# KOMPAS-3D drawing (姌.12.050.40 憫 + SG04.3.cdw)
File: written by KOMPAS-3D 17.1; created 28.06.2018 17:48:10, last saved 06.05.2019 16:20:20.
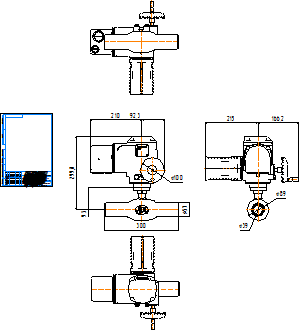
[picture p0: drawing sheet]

Sheet 1: A4, portrait

Title block, sheet 1: name: КШ.12.050.40 СС + SG04.3; material: Внимание! Данный продукт является объектом авторского права ООО «Торговый Дом АДЛ». / Запрещается изменение, копирование, распространение / (в том числе путем копирования на другие сайты и ресурсы в Интернете) / или любое иное использование информации и объектов без предварительного / согласия правообладателя (ООО «Торговый Дом АДЛ»).; sheets: 1; organisation: ООО "Торговый дом АДЛ"; sheet format: A4; stored path: C:\Users\tra\Desktop\2д чертежи\Шаровые краны БИВАЛ\КШ_Бивал_серия_11_12\KOMPAS_2D\КШ.12.050.40 СС + SG04.3.cdw

Views: Проекционный вид 3, Проекционный вид 4
Referenced files in C:\Users\tra\Desktop\2д чертежи\Шаровые краны БИВАЛ\КШ_Бивал_серия_11_12\KOMPAS_2D\: АПТА.0203-1704.04.01 _ Корпус крана Ду50 (Труба по ГОСТ).m3d, АПТА.0203-2615.11.01 _ Шар Ду50.m3d, АПТА.0203-2613.11.01 _ Шток Ду40-50.m3d, АПТА.0203-2613.12.01 _ Корпус штока Ду40-50.m3d, кольцо_проклад_40-50.m3d, шайба_штока_ду40-50.m3d, шайба_фрикц_40-50.m3d, подкладка_для_кольца_40-50.m3d, кольцо_упл_епдм.m3d, кольцо_упл_вит.m3d, СедлоДу50.m3d, Кольцо+опорное_Ду50.m3d, АПТА.0203-1704.03.01 _ Патрубок сварной точенный Ду50 (труба по ГОСТ).m3d, АПТА.0203-2615.02.02 _ Кольцо горловое Ду50.m3d, АПТА.0203-2615.02.03 _ Пружина тарельчатая Ду50.m3d
Referenced files in C:\Users\kka\KOMPAS_Work\Удлинения БИВАЛ ф. ADL\Небюджет\Специальные ISO фланцы\: Фланец Ду40-50.m3d
Referenced files in C:\Users\kka\KOMPAS_Work\!Trash\Электроприводы\: SG 04.3-F07.m3d
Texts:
  kka
  adl
  АПТА.0203-1704.04.01
  Корпус крана Ду50 (Труба по ГОСТ)
  АПТА.0203-2615.11.01
  Шар Ду50
  АПТА.0203-2613.11.01
  Шток Ду40-50
  АПТА.0203-2613.12.01
  Корпус штока Ду40-50
  АПТА.0203-2613.11.06
  Кольцо прокладочное Ду40-50
  АПТА.0203-2613.11.05
  Шайба штока Ду40-50
  АПТА.0203-2613.11.03
  Шайба фрикционная Ду40-50
  АПТА.0203-2613.11.04
  Подкладка для кольца Ду40-50
  Кольцо EPDM 14.3x2.4
  Кольцо Viton 14.3x2.4
  Деталь (локальная)
  АПТА.0203-2615.02.05
  Седловое уплотнение Ду50
  АПТА.0203-2615.02.04
  Кольцо опорное Ду50
  АПТА.0203-1704.03.01
  Патрубок сварной точенный Ду50 (труба по ГОСТ)
  АПТА.0203-2615.02.02
  Кольцо горловое Ду50
  АПТА.0203-2615.02.03
  Пружина тарельчатая Ду50
  ФС.4050.00.01
  Фланец для присоединения  приводов Ду 40-50
  Лит-Масса-Масштаб
  Материал-Предприятие
  Title Specification
  Body Specification ( left align )
  Body Specificaton ( centered )
  Поз.
  Кол.
  Приме-
  чание
  Таблица спецификации
Dimensions and other numbers on the sheet: 1; 1:1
